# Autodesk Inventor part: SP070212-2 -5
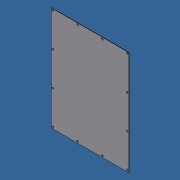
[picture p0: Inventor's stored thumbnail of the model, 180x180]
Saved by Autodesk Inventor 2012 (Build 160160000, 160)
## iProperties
Created: 2012-06
Part Number: SP070212-2 -5
Document SubType Name: Modeling
Designer: Administrator
Density: 1 g/cm^3
Stock Number: 21.9521/1  1/16" ANODIZED AL
Mass: 302.239 g
Surface Area: 3841.75 cm^2
Volume: 302.239 cm^3
Description: MACHINE TO SP062512-2-5
Material: Default
Author: Administrator
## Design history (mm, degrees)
sketch "Sketch1"
  geometry: L1 (11.75, -281.616)-(-365.25, -281.616); L2 (-365.25, -281.616)-(-365.25, 254.4); L3 (-365.25, 254.4)-(11.75, 254.4); L4 (11.75, 254.4)-(11.75, -281.616); L5 (22.362, 256.4)-(-375.863, 256.4) reference; L6 (-367.25, 254)-(-367.25, -283.616) reference; L7 (13.75, 254)-(13.75, -283.616) reference; L8 (-5.25, -283.616)-(-348.25, -283.616) reference; 1 further point
  constraints: 8 end point, 2 parallel, 1 perpendicular
  dimensions: "d24" = 2 distance between parallel lines of L3 L5; "d25" = 2 distance between parallel lines of L6 L2; "d26" = 2 distance between parallel lines of L4 L7; "d27" = 2 distance between parallel lines of L8 L1
extrude "Extrusion1" new body sketch "Sketch1" distance "d1" = 1.5875; taper "d2" = 0 deg
sketch "Sketch2"
  geometry: L1 (-365.25, -281.616)-(-365.25, 254.4) reference; L2 (11.75, -281.616)-(-365.25, -281.616) reference; L3 (11.75, 254.4)-(11.75, -281.616) reference; L4 (-365.25, 254.4)-(11.75, 254.4) reference; L5 (-357.75, -274.116)-(-357.75, 246.9); L6 (-357.75, 246.9)-(4.25, 246.9); L7 (4.25, 246.9)-(4.25, -274.116); L8 (4.25, -274.116)-(-357.75, -274.116); 13 further points
  constraints: 8 end point, 8 point on line, 4 coincident, 3 other
  dimensions: "d3" = 7.5 distance between parallel lines of L7 L3; "d4" = 521.0164 distance of L6.end L7.end (derived); "d5" = 173.67213 distance of point (4.25, 73.228) point (4.25, 246.9) (= 0.333333 x d4); "d6" = 173.67213 distance of point (4.25, -100.444) point (4.25, 73.228) (= d5); "d7" = 361.99999 distance of L7.end L5.start (derived); "d8" = 120.66666 distance of point (-116.417, -274.116) point (4.25, -274.116) (= 0.333333 x d7); "d9" = 120.66666 distance of point (-237.083, -274.116) point (-116.417, -274.116) (= d8); "d10" = 521.0164 distance of L5.start L5.end (derived); "d11" = 173.67213 distance of point (-357.75, 73.228) point (-357.75, 246.9) (= 0.333333 x d10); "d12" = 173.67213 distance of point (-357.75, -100.444) point (-357.75, 73.228) (= d11); "d13" = 361.99999 distance of L5.end L6.end (derived); "d14" = 120.66666 distance of point (-237.083, 246.9) point (-357.75, 246.9) (= 0.333333 x d13); "d15" = 120.66666 distance of point (-116.417, 246.9) point (-237.083, 246.9) (= d14)
hole "Hole1" sketch "Sketch2" at (4.25, -274.116), (-116.417, -274.116), (-237.083, -274.116), (-357.75, -274.116), (-357.75, 246.9), (-357.75, -100.444), (-357.75, 73.228), (-237.083, 246.9), (-116.417, 246.9), (4.25, 73.228), (4.25, -100.444), (4.25, 246.9) diameter "d16" = 4.3; stored, may be unused: countersink angle "d20" = 90 deg, drill point angle "d22" = 118 deg; dims "d17" = 12.7, "d18" = 9, "d19" = 6.35, "d21" = 19.05
body "Solid1"
node "Reference5"
node "Reference6"
node "Reference7"
node "Reference8"
